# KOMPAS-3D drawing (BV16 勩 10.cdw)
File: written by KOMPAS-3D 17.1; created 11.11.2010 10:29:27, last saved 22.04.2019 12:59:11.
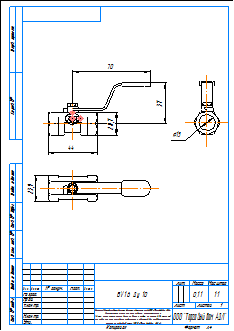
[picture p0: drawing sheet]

Sheet 1: A4, portrait

Title block, sheet 1: name: BV16 Ду 10; material: Внимание! Данный продукт является объектом авторского права ООО «Торговый Дом АДЛ». / Запрещается изменение, копирование, распространение / (в том числе путем копирования на другие сайты и ресурсы в Интернете) / или любое иное использование информации и объектов без предварительного / согласия правообладателя (ООО «Торговый Дом АДЛ»).; mass: 0,11; scale: 1:1; sheets: 1; organisation: ООО "Торговый дом АДЛ"; sheet format: A4; stored path: \\adlc.lan\data\АДЛ_ПКД\3D-модели\ADL production\Краны шаровые серии BV\BV16\KOMPAS 2D\BV16 Ду 10.cdw

Views: Спереди 1, Проекционный вид 2, Проекционный вид 3
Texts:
  user
  adl
Dimensions and other numbers on the sheet: 20,7; 44; 37; 70; 15; 23,9; 1:1; 1; 0,11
